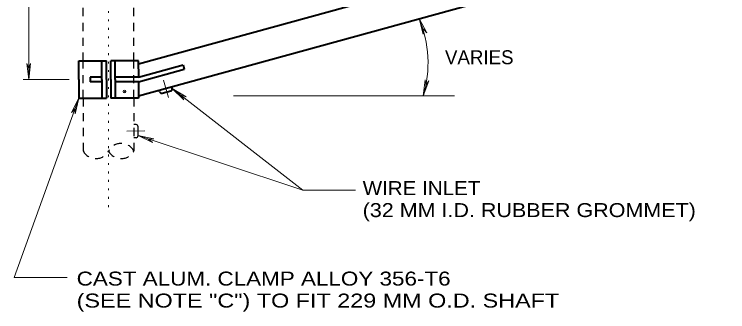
# Model space of a CAD drawing. Extents: x 312583 to 312854, y 144419 to 144597.
# Drawn here: x 312724.19 to 312762.98, y 144522.02 to 144538.22 of the extents above; entities that cross this region are included whole.
import ezdxf

# ---------------------------------------------------------------- set-up
doc = ezdxf.new("R2010")
doc.units = 0
doc.header["$LTSCALE"] = 0.3
doc.header["$PDMODE"] = 32
doc.header["$PDSIZE"] = 0.15
doc.linetypes.add('DOTTED', pattern=[1.5, 0.3, -1.2])
doc.linetypes.add('SHORT_DASHED', pattern=[2.7, 1.5, -1.2])
doc.layers.add('1', color=7, linetype='Continuous', lineweight=13)

msp = doc.modelspace()

# ---------------------------------------------------------------- linework, layer by layer
at = {"layer": '1', "linetype": 'DOTTED'}
msp.add_line((312729.3174, 144527.7179), (312729.3174, 144572.2382), dxfattribs=at)
at = {"layer": '1', "lineweight": 40}
for p, q in [((312730.935, 144535.5226), (312830.111, 144562.8236)), ((312730.9427, 144533.7822), (312830.5557, 144561.2059)), ((312727.6997, 144535.6836), (312729.1947, 144535.6836)), ((312727.6997, 144534.6716), (312727.6997, 144535.6836)), ((312728.957, 144534.6716), (312728.957, 144535.6836)), ((312729.1947, 144534.6716), (312729.1947, 144535.6836)), ((312730.935, 144535.6836), (312729.44, 144535.6836)), ((312729.44, 144534.6716), (312729.44, 144535.6836)), ((312729.6777, 144534.6716), (312729.6777, 144535.6836)), ((312730.9274, 144535.6836), (312730.935, 144534.7866)), ((312730.935, 144534.7866), (312733.3654, 144535.4612)), ((312730.935, 144534.5412), (312733.4267, 144535.2312)), ((312733.3654, 144535.4612), (312733.4267, 144535.2312)), ((312728.3207, 144534.7866), (312728.3207, 144534.5489)), ((312728.957, 144534.7866), (312728.3207, 144534.7866)), ((312730.935, 144534.7866), (312729.6777, 144534.7866)), ((312727.6997, 144534.6716), (312727.6997, 144533.6519)), ((312728.957, 144534.5489), (312728.3207, 144534.5489)), ((312728.957, 144534.6716), (312728.957, 144533.6519)), ((312729.1947, 144534.6716), (312729.1947, 144533.6519)), ((312729.44, 144534.6716), (312729.44, 144533.6519)), ((312729.6777, 144534.6716), (312729.6777, 144533.6519)), ((312730.958, 144534.5489), (312729.6777, 144534.5489)), ((312730.935, 144534.5412), (312730.9427, 144533.6519)), ((312732.0927, 144533.9892), (312732.0697, 144534.0889)), ((312732.2384, 144533.9202), (312732.6984, 144534.0506)), ((312732.7827, 144534.1809), (312732.7597, 144534.2806))]:
    msp.add_line(p, q, dxfattribs=at)
at = {"layer": '1'}
for p, q in [((312724.9722, 144534.6716), (312724.9722, 144549.0466)), ((312746.207, 144537.9836), (312746.414, 144537.1402)), ((312746.207, 144537.9836), (312746.6134, 144537.2169)), ((312746.414, 144537.1402), (312746.414, 144537.4316)), ((312746.6134, 144537.2169), (312746.414, 144537.4316)), ((312724.8649, 144535.5379), (312724.9722, 144535.2619)), ((312724.9722, 144534.6716), (312724.8649, 144535.5379)), ((312725.0795, 144535.5379), (312724.9722, 144535.2619)), ((312724.9722, 144534.6716), (312725.0795, 144535.5379)), ((312727.1707, 144534.6716), (312724.6685, 144534.6716)), ((312732.3074, 144534.6332), (312732.568, 144533.6902)), ((312746.4294, 144533.7822), (312746.529, 144534.6486)), ((312746.4294, 144533.7822), (312746.736, 144534.6026)), ((312746.529, 144534.6486), (312746.5674, 144534.3572)), ((312746.736, 144534.6026), (312746.5674, 144534.3572)), ((312732.7827, 144534.1809), (312733.4037, 144533.5599)), ((312732.7827, 144534.1809), (312733.534, 144533.7286)), ((312727.6997, 144533.6519), (312727.3087, 144532.8699)), ((312727.6997, 144533.6519), (312727.508, 144532.8009)), ((312733.4037, 144533.5599), (312733.2504, 144533.8206)), ((312733.534, 144533.7286), (312733.2504, 144533.8206)), ((312736.1177, 144533.7822), (312748.1237, 144533.7822)), ((312727.3087, 144532.8699), (312727.5004, 144533.0922)), ((312727.508, 144532.8009), (312727.5004, 144533.0922)), ((312730.3064, 144531.8579), (312731.2877, 144531.8656)), ((312730.9274, 144531.6126), (312731.7094, 144531.2446)), ((312730.9274, 144531.6126), (312731.7784, 144531.4439)), ((312731.7784, 144531.4439), (312731.487, 144531.4286)), ((312731.7094, 144531.2446), (312731.487, 144531.4286)), ((312739.8744, 144528.6456), (312742.7494, 144528.6456))]:
    msp.add_line(p, q, dxfattribs=at)
at = {"layer": '1', "linetype": 'SHORT_DASHED', "lineweight": 25}
for p, q in [((312727.9374, 144535.6836), (312727.9374, 144548.0269)), ((312730.6974, 144535.6836), (312730.6974, 144548.0269)), ((312727.9374, 144533.6519), (312727.9374, 144535.6836)), ((312730.6974, 144533.6519), (312730.6974, 144535.6836)), ((312727.9374, 144533.6519), (312727.9374, 144530.7769)), ((312730.6974, 144533.6519), (312730.6974, 144530.7769))]:
    msp.add_line(p, q, dxfattribs=at)
at = {"layer": '1', "lineweight": 25}
for p, q in [((312730.82, 144532.2106), (312730.6974, 144532.2106)), ((312730.9274, 144531.6126), (312730.9274, 144532.0956)), ((312730.82, 144531.4976), (312730.6897, 144531.4976))]:
    msp.add_line(p, q, dxfattribs=at)
at = {"layer": '1'}
for points in [[(312730.9274, 144531.6126), (312739.8744, 144528.6456), (312732.7827, 144534.1809)], [(312727.6997, 144533.6519), (312724.1884, 144523.8846), (312727.0634, 144523.8846)]]:
    msp.add_lwpolyline(points, dxfattribs=at)
at = {"layer": '1', "lineweight": 40}
for points in [[(312727.6997, 144533.6519), (312728.957, 144533.6519), (312729.1947, 144533.6519)], [(312730.935, 144533.6519), (312729.6777, 144533.6519), (312729.44, 144533.6519)]]:
    msp.add_lwpolyline(points, dxfattribs=at)
at = {"layer": '1'}
msp.add_arc((312740.3748, 144535.5596), 6.3128, 343.65192, 22.57618, dxfattribs=at)
at = {"layer": '1', "lineweight": 40}
for centre, start, end in [((312732.2039, 144534.0357), 202.50814, 285.66313), ((312732.6668, 144534.1633), 285.1627, 8.24485)]:
    msp.add_arc(centre, 0.1193, start, end, dxfattribs=at)
at = {"layer": '1', "lineweight": 25}
for centre, start, end in [((312730.8045, 144532.0949), 359.7352, 82.81735), ((312730.8044, 144531.6147), 277.08064, 0.23563)]:
    msp.add_arc(centre, 0.1193, start, end, dxfattribs=at)
at = {"layer": '1', "linetype": 'SHORT_DASHED', "lineweight": 25}
for centre, start, end in [((312730.0052, 144530.4102), 27.93563, 152.06437), ((312728.6276, 144531.1407), 207.93563, 332.06437), ((312730.0052, 144531.1407), 207.93563, 332.06437)]:
    msp.add_arc(centre, 0.7796, start, end, dxfattribs=at)
at = {"layer": '1'}
msp.add_point((312730.1837, 144534.0122), dxfattribs=at)

# ---------------------------------------------------------------- texts
msp.add_text('VARIES', height=0.76, dxfattribs=at).set_placement((312747.6081, 144535.5005))
for s, width, p in [('WIRE INLET', 1.1, (312743.1346, 144528.3743)), ('(32 MM I.D. RUBBER GROMMET)', 1.15, (312743.1346, 144527.1773)), ('CAST ALUM. CLAMP ALLOY 356-T6', 1.2, (312727.5808, 144523.4484)), ('(SEE NOTE "C") TO FIT 229 MM O.D. SHAFT ', 1.25, (312727.5808, 144522.2514))]:
    msp.add_text(s, height=0.76, dxfattribs=dict(at, width=width)).set_placement(p)

doc.saveas('drawing.dxf')
